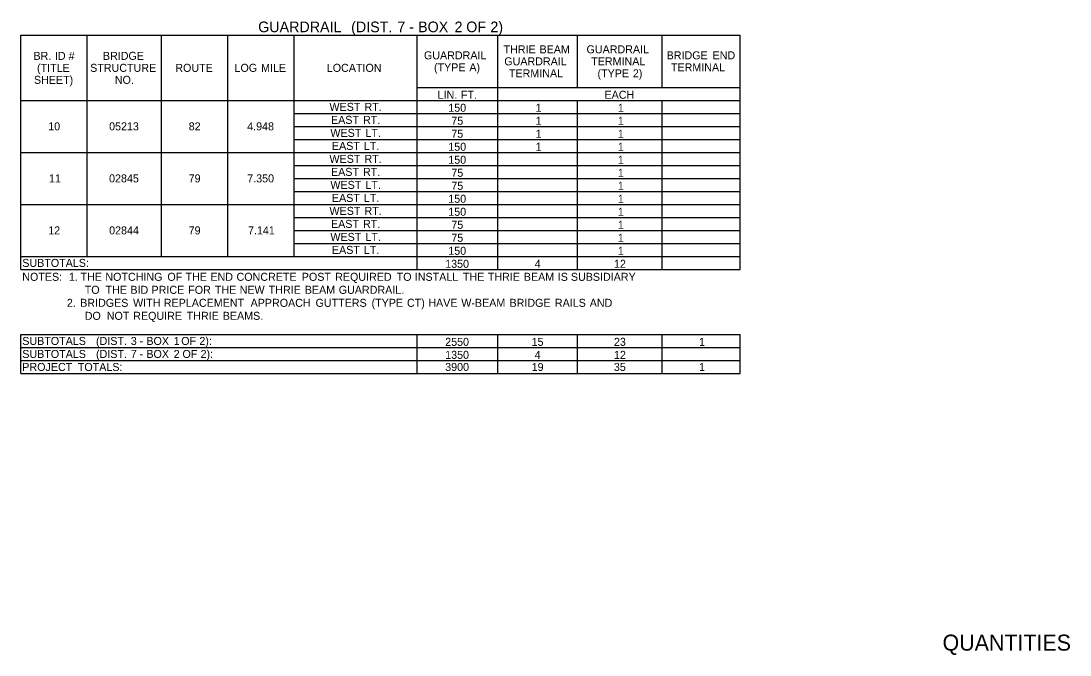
# Model space of a CAD drawing. Extents: x 544478 to 1930787, y -1948294 to 596640.
# Drawn here: x 546902 to 547689, y -1947044 to -1946569 of the extents above; entities that cross this region are included whole.
import ezdxf

# ---------------------------------------------------------------- set-up
doc = ezdxf.new("R2010")
doc.units = 0
doc.layers.add('Default', color=7, linetype='Continuous')
doc.layers.add('R_Border', color=7, linetype='Continuous')

msp = doc.modelspace()

# ---------------------------------------------------------------- linework, layer by layer
at = {"layer": 'Default'}
for p, q in [((546902.33, -1946579.64), (547441.51, -1946579.64)), ((546902.33, -1946755.14), (546902.33, -1946579.64)), ((546952.06, -1946745.39), (546952.06, -1946579.64)), ((547007.63, -1946745.39), (547007.63, -1946579.64)), ((547057.36, -1946745.39), (547057.36, -1946579.64)), ((547107.08, -1946745.39), (547107.08, -1946579.64)), ((547199.22, -1946755.14), (547199.22, -1946579.64)), ((547259.67, -1946755.14), (547259.67, -1946579.64)), ((547319.63, -1946618.64), (547319.63, -1946579.64)), ((547383.01, -1946618.64), (547383.01, -1946579.64)), ((547441.51, -1946755.14), (547441.51, -1946579.64)), ((547199.22, -1946618.64), (547441.51, -1946618.64)), ((547259.67, -1946755.14), (547259.67, -1946618.64)), ((546902.33, -1946628.39), (547441.51, -1946628.39)), ((547319.63, -1946755.14), (547319.63, -1946628.39)), ((547319.63, -1946755.14), (547319.63, -1946628.39)), ((547383.01, -1946755.14), (547383.01, -1946628.39)), ((547383.01, -1946755.14), (547383.01, -1946628.39)), ((547107.08, -1946638.14), (547441.51, -1946638.14)), ((547107.08, -1946647.89), (547199.22, -1946647.89)), ((547107.08, -1946647.89), (547441.51, -1946647.89)), ((547107.08, -1946657.64), (547441.51, -1946657.64)), ((546902.33, -1946667.39), (547441.51, -1946667.39)), ((547107.08, -1946667.39), (547199.22, -1946667.39)), ((547199.22, -1946667.39), (547441.51, -1946667.39)), ((547107.08, -1946677.14), (547441.51, -1946677.14)), ((547107.08, -1946686.89), (547199.22, -1946686.89)), ((547107.08, -1946686.89), (547441.51, -1946686.89)), ((547107.08, -1946696.64), (547441.51, -1946696.64)), ((546902.33, -1946706.39), (547441.51, -1946706.39)), ((547107.08, -1946706.39), (547199.22, -1946706.39)), ((547199.22, -1946706.39), (547441.51, -1946706.39)), ((547107.08, -1946716.14), (547441.51, -1946716.14)), ((547107.08, -1946725.89), (547199.22, -1946725.89)), ((547107.08, -1946725.89), (547441.51, -1946725.89)), ((547107.08, -1946735.64), (547441.51, -1946735.64)), ((546902.33, -1946745.39), (547441.51, -1946745.39)), ((547107.08, -1946745.39), (547199.22, -1946745.39)), ((547199.22, -1946745.39), (547441.51, -1946745.39)), ((546902.33, -1946755.14), (547441.51, -1946755.14)), ((546902.33, -1946803.89), (547441.51, -1946803.89)), ((546902.33, -1946803.89), (547441.51, -1946803.89)), ((546902.33, -1946833.14), (546902.33, -1946803.89)), ((547199.22, -1946833.14), (547199.22, -1946803.89)), ((547259.67, -1946833.14), (547259.67, -1946803.89)), ((547259.67, -1946833.14), (547259.67, -1946803.89)), ((547319.63, -1946833.14), (547319.63, -1946803.89)), ((547319.63, -1946833.14), (547319.63, -1946803.89)), ((547383.01, -1946833.14), (547383.01, -1946803.89)), ((547383.01, -1946833.14), (547383.01, -1946803.89)), ((547441.51, -1946813.64), (547441.51, -1946803.89)), ((546902.33, -1946813.64), (547441.51, -1946813.64)), ((547441.51, -1946833.14), (547441.51, -1946813.64)), ((546902.33, -1946823.39), (547441.51, -1946823.39)), ((546902.33, -1946833.14), (547441.51, -1946833.14))]:
    msp.add_line(p, q, dxfattribs=at)

# ---------------------------------------------------------------- texts
for s, height, p in [('GUARDRAIL', 8, (547080.14, -1946577.31)), (' (DIST.', 8, (547146.87, -1946577.31)), (' 7', 8, (547181.49, -1946577.31)), (' BOX', 8, (547197.06, -1946577.31)), (' 2', 8, (547224.38, -1946577.31)), (' OF', 8, (547233.13, -1946577.31)), (' 2)', 8, (547251.24, -1946577.31)), (' -', 8, (547190.32, -1946577.31)), ('BR.', 6, (546911.67, -1946598.02)), (' ID', 6, (546925.53, -1946598.02)), (' #', 6, (546935.83, -1946598.02)), ('BRIDGE', 6, (546963.75, -1946598.02)), ('GUARDRAIL', 6, (547204.42, -1946597.64)), ('THRIE', 6, (547264.07, -1946593.14)), (' BEAM', 6, (547288.81, -1946593.14)), ('GUARDRAIL', 6, (547326.29, -1946593.14)), ('BRIDGE', 6, (547386.35, -1946597.64)), (' END', 6, (547418.54, -1946597.64)), ('(TITLE', 6, (546914.36, -1946607.02)), ('STRUCTURE', 6, (546954.2, -1946607.02)), ('ROUTE', 6, (547018.03, -1946607.02)), ('LOG', 6, (547062.42, -1946607.02)), (' MILE', 6, (547080.08, -1946607.02)), ('LOCATION', 6, (547131.6, -1946607.02)), ('(TYPE', 6, (547211.94, -1946606.64)), (' A)', 6, (547236.21, -1946606.64)), ('GUARDRAIL', 6, (547264.63, -1946602.14)), ('TERMINAL', 6, (547329.79, -1946602.14)), ('TERMINAL', 6, (547389.56, -1946606.64)), ('TERMINAL', 6, (547268.12, -1946611.14)), ('(TYPE', 6, (547334.51, -1946611.14)), (' 2)', 6, (547358.78, -1946611.14)), ('SHEET)', 6, (546912.04, -1946616.02)), ('NO.', 6, (546972.68, -1946616.02)), ('LIN.', 6, (547214.65, -1946627.19)), (' FT.', 6, (547229.91, -1946627.19)), ('EACH', 6, (547339.76, -1946627.19)), ('WEST', 6, (547133.57, -1946636.27)), (' RT.', 6, (547157.63, -1946636.27)), ('150', 6, (547222.66, -1946636.94)), ('1', 6, (547288.09, -1946636.94)), ('1', 6, (547349.76, -1946636.94)), ('EAST', 6, (547134.73, -1946646.02)), (' RT.', 6, (547156.47, -1946646.02)), ('10', 6, (546922.74, -1946650.89)), ('05213', 6, (546968.38, -1946650.89)), ('82', 6, (547028.06, -1946650.89)), ('4.948', 6, (547071.92, -1946650.89)), ('75', 6, (547224.95, -1946646.69)), ('1', 6, (547288.09, -1946646.69)), ('1', 6, (547349.76, -1946646.69)), ('WEST', 6, (547134.27, -1946655.77)), (' LT.', 6, (547158.32, -1946655.77)), ('75', 6, (547224.95, -1946656.44)), ('1', 6, (547288.09, -1946656.44)), ('1', 6, (547349.76, -1946656.44)), ('EAST', 6, (547135.43, -1946665.52)), (' LT.', 6, (547157.16, -1946665.52)), ('150', 6, (547222.66, -1946666.19)), ('1', 6, (547288.09, -1946666.19)), ('1', 6, (547349.76, -1946666.19)), ('WEST', 6, (547133.57, -1946675.27)), (' RT.', 6, (547157.63, -1946675.27)), ('150', 6, (547222.66, -1946675.94)), ('1', 6, (547349.76, -1946675.94)), ('EAST', 6, (547134.73, -1946685.02)), (' RT.', 6, (547156.47, -1946685.02)), ('75', 6, (547224.95, -1946685.69)), ('1', 6, (547349.76, -1946685.69)), ('11', 6, (546923.3, -1946689.89)), ('02845', 6, (546968.36, -1946689.89)), ('79', 6, (547028.02, -1946689.89)), ('7.350', 6, (547071.94, -1946689.89)), ('WEST', 6, (547134.27, -1946694.77)), (' LT.', 6, (547158.32, -1946694.77)), ('75', 6, (547224.95, -1946695.44)), ('1', 6, (547349.76, -1946695.44)), ('EAST', 6, (547135.43, -1946704.52)), (' LT.', 6, (547157.16, -1946704.52)), ('150', 6, (547222.66, -1946705.19)), ('1', 6, (547349.76, -1946705.19)), ('WEST', 6, (547133.57, -1946714.27)), (' RT.', 6, (547157.63, -1946714.27)), ('150', 6, (547222.66, -1946714.94)), ('1', 6, (547349.76, -1946714.94)), ('EAST', 6, (547134.73, -1946724.02)), (' RT.', 6, (547156.47, -1946724.02)), ('75', 6, (547224.95, -1946724.69)), ('1', 6, (547349.76, -1946724.69)), ('12', 6, (546922.76, -1946728.89)), ('02844', 6, (546968.4, -1946728.89)), ('79', 6, (547028.02, -1946728.89)), ('7.141', 6, (547072.51, -1946728.89)), ('WEST', 6, (547134.27, -1946733.77)), (' LT.', 6, (547158.32, -1946733.77)), ('75', 6, (547224.95, -1946734.44)), ('1', 6, (547349.76, -1946734.44)), ('EAST', 6, (547135.43, -1946743.52)), (' LT.', 6, (547157.16, -1946743.52)), ('150', 6, (547222.66, -1946744.19)), ('1', 6, (547349.76, -1946744.19)), ('SUBTOTALS:', 6, (546903.31, -1946753.27)), ('1350', 6, (547220.33, -1946753.94)), ('4', 6, (547287.42, -1946753.94)), ('12', 6, (547346.87, -1946753.94)), ('NOTES:', 6, (546903.31, -1946763.69)), ('  1.', 6, (546933.79, -1946763.69)), (' THE', 6, (546944.7, -1946763.69)), (' NOTCHING', 6, (546963.35, -1946763.69)), (' OF', 6, (547009.86, -1946763.69)), (' THE', 6, (547023.45, -1946763.69)), (' END', 6, (547042.1, -1946763.69)), (' CONCRETE', 6, (547061.68, -1946763.69)), (' POST', 6, (547110.61, -1946763.69)), (' REQUIRED', 6, (547135.6, -1946763.69)), (' TO', 6, (547181.73, -1946763.69)), (' INSTALL', 6, (547195.33, -1946763.69)), (' THE', 6, (547231.37, -1946763.69)), (' THRIE', 6, (547250.02, -1946763.69)), (' BEAM', 6, (547277.05, -1946763.69)), (' IS', 6, (547302.51, -1946763.69)), (' SUBSIDIARY', 6, (547312.32, -1946763.69)), ('                     TO', 6, (546903.31, -1946773.44)), (' THE', 6, (546963.46, -1946773.44)), (' BID', 6, (546982.11, -1946773.44)), (' PRICE', 6, (546997.96, -1946773.44)), (' FOR', 6, (547025.47, -1946773.44)), (' THE', 6, (547045.38, -1946773.44)), (' NEW', 6, (547064.03, -1946773.44)), (' THRIE', 6, (547085.82, -1946773.44)), (' BEAM', 6, (547112.85, -1946773.44)), (' GUARDRAIL.', 6, (547138.31, -1946773.44)), ('               2.', 6, (546903.31, -1946783.19)), (' BRIDGES', 6, (546944.48, -1946783.19)), (' WITH', 6, (546984.11, -1946783.19)), (' REPLACEMENT', 6, (547007.17, -1946783.19)), (' APPROACH', 6, (547072.23, -1946783.19)), (' GUTTERS', 6, (547120.93, -1946783.19)), (' (TYPE', 6, (547162.88, -1946783.19)), (' CT)', 6, (547189.45, -1946783.19)), (' HAVE', 6, (547205.45, -1946783.19)), (' W-BEAM', 6, (547230.16, -1946783.19)), (' BRIDGE', 6, (547266.32, -1946783.19)), (' RAILS', 6, (547300.34, -1946783.19)), (' AND', 6, (547326.46, -1946783.19)), ('                     DO', 6, (546903.31, -1946792.94)), (' NOT', 6, (546964.39, -1946792.94)), (' REQUIRE', 6, (546984.25, -1946792.94)), (' THRIE', 6, (547024.33, -1946792.94)), (' BEAMS.', 6, (547051.36, -1946792.94)), ('SUBTOTALS', 6, (546903.31, -1946811.77)), ('  (DIST.', 6, (546954.13, -1946811.77)), (' 3', 6, (546982.43, -1946811.77)), (' BOX', 6, (546994.11, -1946811.77)), (' OF', 6, (547020.23, -1946811.77)), (' 2):', 6, (547033.81, -1946811.77)), (' -', 6, (546989.05, -1946811.77)), (' 1', 6, (547014.6, -1946811.77)), ('2550', 6, (547220.33, -1946812.44)), ('15', 6, (547285.12, -1946812.44)), ('23', 6, (547346.84, -1946812.44)), ('1', 6, (547410.61, -1946812.44)), ('SUBTOTALS', 6, (546903.31, -1946821.52)), ('  (DIST.', 6, (546954.13, -1946821.52)), (' 7', 6, (546982.43, -1946821.52)), (' -', 6, (546989.04, -1946821.52)), (' BOX', 6, (546994.1, -1946821.52)), (' 2', 6, (547014.59, -1946821.52)), (' OF', 6, (547021.16, -1946821.52)), (' 2):', 6, (547034.74, -1946821.52)), ('1350', 6, (547220.33, -1946822.19)), ('4', 6, (547287.42, -1946822.19)), ('12', 6, (547346.87, -1946822.19)), ('PROJECT', 6, (546903.31, -1946831.27)), (' TOTALS:', 6, (546942.73, -1946831.27)), ('3900', 6, (547220.33, -1946831.27)), ('19', 6, (547285.18, -1946831.27)), ('35', 6, (547346.78, -1946831.27)), ('1', 6, (547410.61, -1946831.27))]:
    msp.add_text(s, height=height, dxfattribs=at).set_placement(p)
at = {"layer": 'R_Border'}
msp.add_text('QUANTITIES', height=12, rotation=360, dxfattribs=at).set_placement((547593.16, -1947040.95))

doc.saveas('drawing.dxf')
